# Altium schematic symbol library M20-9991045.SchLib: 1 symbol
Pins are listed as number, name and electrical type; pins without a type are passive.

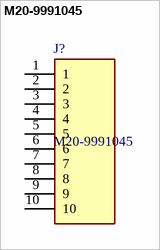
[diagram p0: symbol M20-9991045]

## M20-9991045
designator J?
M20: 10 Pos Plug SIL Straight 3mm THT Connector 6.1mm pin Gold; Manufacturer_Name: Harwin; Geometry.Height: 8.64mm
footprint HDRV10W64P0X254_1X10_2540X254X864P
pins: 1, 2, 3, 4, 5, 6, 7, 8, 9, 10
